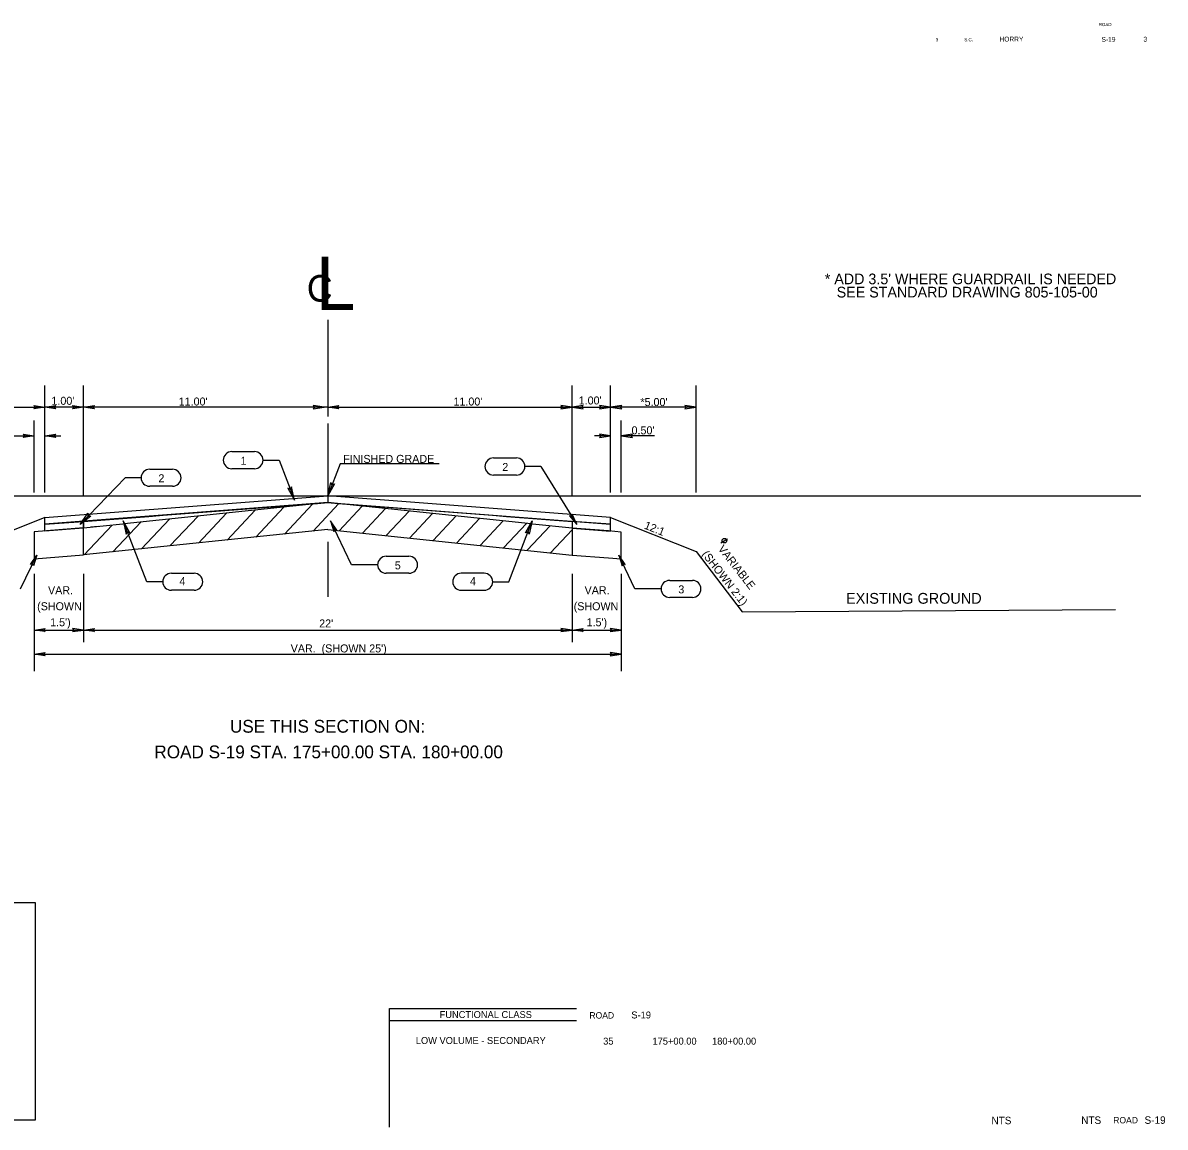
# Model space of a CAD drawing. Extents: x -8855 to -7217, y 44218 to 45252.
# Drawn here: x -8287 to -7217, y 44218 to 45252 of the extents above; entities that cross this region are included whole.
import ezdxf

# ---------------------------------------------------------------- set-up
doc = ezdxf.new("R2010")
doc.units = 0
for name, color, linetype in [('Default', 7, 'Continuous'), ('RD_EX_Misc', 7, 'Continuous'), ('RD_SHT_Bndy', 7, 'Continuous'), ('RD_SHT_TX', 7, 'Continuous'), ('RD_Sketch5', 7, 'Continuous'), ('RD_TX_TypSect', 7, 'Continuous'), ('RD_XS_Greenside', 7, 'Continuous')]:
    doc.layers.add(name, color=color, linetype=linetype)

msp = doc.modelspace()

# ---------------------------------------------------------------- linework, layer by layer
at = {"layer": 'Default'}
for p, q in [((-8825.7, 44809.3), (-8001.4, 44809.3)), ((-8001.4, 44809.3), (-7239.8, 44809.3)), ((-7626.9, 44768.9), (-7633.1, 44765.2)), ((-7613.3, 44700.8), (-7263.6, 44702.9))]:
    msp.add_line(p, q, dxfattribs=at)
for points in [[(-8266.4, 44892.5), (-8276.8, 44891), (-8275.2, 44892.5), (-8276.8, 44894)], [(-8266.4, 44892.5), (-8256, 44894), (-8257.6, 44892.5), (-8256, 44891)], [(-8230.3, 44892.5), (-8240.6, 44891), (-8239, 44892.5), (-8240.6, 44894)], [(-8230.3, 44892.5), (-8219.9, 44894), (-8221.5, 44892.5), (-8219.9, 44891)], [(-8004.6, 44892.5), (-8015, 44894), (-8013.4, 44892.5), (-8015, 44891)], [(-8001.4, 44892.5), (-7991, 44894), (-7992.6, 44892.5), (-7991, 44891)], [(-7772.5, 44892.5), (-7782.9, 44894), (-7781.3, 44892.5), (-7782.9, 44891)], [(-7772.5, 44892.5), (-7762.2, 44891), (-7763.8, 44892.5), (-7762.2, 44894)], [(-7736.4, 44892.5), (-7746.8, 44894), (-7745.2, 44892.5), (-7746.8, 44891)], [(-7736.4, 44892.5), (-7726, 44891), (-7727.6, 44892.5), (-7726, 44894)], [(-7656.4, 44892.5), (-7666.8, 44894), (-7665.2, 44892.5), (-7666.8, 44891)], [(-8276.4, 44865.6), (-8286.8, 44864.1), (-8285.2, 44865.6), (-8286.8, 44867.1)], [(-8266.4, 44865.6), (-8256, 44867.1), (-8257.6, 44865.6), (-8256, 44864.1)], [(-7736.4, 44865.6), (-7746.8, 44867.1), (-7745.2, 44865.6), (-7746.8, 44864.1)], [(-7726.4, 44865.6), (-7716, 44864.1), (-7717.6, 44865.6), (-7716, 44867.1)], [(-8230.3, 44785.4), (-8230.3, 44779.2), (-8266.4, 44776.3), (-8266.4, 44782.7)], [(-7998.8, 44786), (-7995.7, 44775.9), (-7995, 44778), (-7993, 44777.2)], [(-7772.5, 44785.5), (-7772.5, 44779.2), (-7736.4, 44776.3), (-7736.4, 44782.7)], [(-8274, 44753.9), (-8277.1, 44743.9), (-8277.8, 44746), (-8279.9, 44745.2)], [(-7728.8, 44753.9), (-7725.7, 44743.9), (-7725, 44746), (-7722.9, 44745.2)], [(-8276.4, 44683.7), (-8266, 44685.2), (-8267.6, 44683.7), (-8266, 44682.2)], [(-8230.3, 44683.7), (-8240.6, 44685.2), (-8239, 44683.7), (-8240.6, 44682.2)], [(-8230.3, 44683.7), (-8219.9, 44685.2), (-8221.5, 44683.7), (-8219.9, 44682.2)], [(-7772.5, 44683.7), (-7782.9, 44685.2), (-7781.3, 44683.7), (-7782.9, 44682.2)], [(-7772.5, 44683.7), (-7762.2, 44685.2), (-7763.8, 44683.7), (-7762.2, 44682.2)], [(-7726.4, 44683.7), (-7736.8, 44685.2), (-7735.2, 44683.7), (-7736.8, 44682.2)], [(-8276.4, 44661), (-8266, 44662.5), (-8267.6, 44661), (-8266, 44659.5)], [(-7726.4, 44661), (-7736.8, 44662.5), (-7735.2, 44661), (-7736.8, 44659.5)]]:
    msp.add_lwpolyline(points, close=True, dxfattribs=at)
msp.add_circle((-7629.8, 44767.4), 2.17, dxfattribs=at)
at = {"layer": 'RD_EX_Misc'}
for p, q in [((-8001.4, 44974.2), (-8001.4, 44883.7)), ((-8266.4, 44812.4), (-8266.4, 44912.7)), ((-8230.3, 44809.3), (-8230.3, 44912.7)), ((-7772.5, 44809.3), (-7772.5, 44912.7)), ((-7736.4, 44812.4), (-7736.4, 44912.7)), ((-7736.4, 44812.4), (-7736.4, 44912.7)), ((-7656.4, 44812.4), (-7656.4, 44912.6)), ((-8346.4, 44892.5), (-8266.4, 44892.5)), ((-8230.3, 44892.5), (-8266.4, 44892.5)), ((-8001.4, 44892.5), (-8230.3, 44892.5)), ((-8001.4, 44892.5), (-7772.5, 44892.5)), ((-7772.5, 44892.5), (-7736.4, 44892.5)), ((-7656.4, 44892.5), (-7736.4, 44892.5)), ((-8276.4, 44812.4), (-8276.4, 44880.1)), ((-8001.4, 44877), (-8001.4, 44809.3)), ((-7726.4, 44812.4), (-7726.4, 44880.1)), ((-8307.4, 44865.6), (-8276.4, 44865.6)), ((-8266.4, 44865.6), (-8251.4, 44865.6)), ((-7736.4, 44865.6), (-7751.4, 44865.6)), ((-7695.4, 44865.6), (-7726.4, 44865.6)), ((-8091.3, 44850.8), (-8070, 44850.8)), ((-7846.1, 44844.9), (-7824.7, 44844.9)), ((-8168.2, 44834.3), (-8146.8, 44834.3)), ((-8070, 44834.8), (-8091.3, 44834.8)), ((-8062, 44842.8), (-8047, 44842.8)), ((-7801.7, 44836.9), (-7816.7, 44836.9)), ((-7801.7, 44836.9), (-7768.1, 44782.6)), ((-8191.2, 44826.3), (-8233.4, 44782.6)), ((-8176.2, 44826.3), (-8191.2, 44826.3)), ((-7824.7, 44828.9), (-7846.1, 44828.9)), ((-8146.8, 44818.3), (-8168.2, 44818.3)), ((-8266.4, 44789), (-8001.4, 44809.3)), ((-8001.4, 44803), (-8266.4, 44782.7)), ((-8001.4, 44803), (-8192, 44783.2)), ((-8015.2, 44776.4), (-7991.2, 44802)), ((-8015.2, 44776.4), (-7991.2, 44802)), ((-7736.4, 44789), (-8001.4, 44809.3)), ((-8001.4, 44809.3), (-8001.4, 44803)), ((-8001.4, 44809.3), (-8001.4, 44803)), ((-7810.7, 44783.2), (-8001.4, 44803)), ((-8001.4, 44803), (-7736.4, 44782.7)), ((-8122.4, 44765.2), (-8096.1, 44793.1)), ((-8095.6, 44768), (-8069.3, 44795.9)), ((-8068.8, 44770.8), (-8042.6, 44798.7)), ((-8042, 44773.6), (-8015.8, 44801.5)), ((-7990.8, 44776.7), (-7969.2, 44799.7)), ((-7990.8, 44776.7), (-7969.2, 44799.7)), ((-7968.7, 44774.4), (-7947.2, 44797.4)), ((-7968.7, 44774.4), (-7947.2, 44797.4)), ((-7946.7, 44772.1), (-7925.2, 44795.1)), ((-7946.7, 44772.1), (-7925.2, 44795.1)), ((-7924.7, 44769.8), (-7903.2, 44792.8)), ((-7924.7, 44769.8), (-7903.2, 44792.8)), ((-8266.4, 44782.7), (-8266.4, 44789)), ((-8230.3, 44785.4), (-8168.9, 44790.1)), ((-8230.3, 44779.2), (-8230.3, 44785.4)), ((-8193.3, 44783), (-8230.3, 44779.2)), ((-8229.5, 44754), (-8203.3, 44782)), ((-8216.3, 44780.6), (-8223.2, 44779.9)), ((-8202.7, 44756.8), (-8176.5, 44784.8)), ((-8202.7, 44756.8), (-8176.5, 44784.8)), ((-8170.9, 44728.9), (-8193, 44785.9)), ((-8176, 44759.6), (-8149.7, 44787.6)), ((-8149.2, 44762.4), (-8122.9, 44790.4)), ((-7979.2, 44744.8), (-7998.8, 44786)), ((-7902.7, 44767.5), (-7881.1, 44790.5)), ((-7902.7, 44767.5), (-7881.1, 44790.5)), ((-7880.7, 44765.2), (-7859.1, 44788.2)), ((-7880.7, 44765.2), (-7859.1, 44788.2)), ((-7880.7, 44765.2), (-7859.1, 44788.2)), ((-7858.7, 44762.9), (-7837.1, 44785.9)), ((-7858.7, 44762.9), (-7837.1, 44785.9)), ((-7858.7, 44762.9), (-7837.1, 44785.9)), ((-7836.7, 44760.7), (-7815.1, 44783.6)), ((-7836.7, 44760.7), (-7815.1, 44783.6)), ((-7833.9, 44790.1), (-7772.5, 44785.5)), ((-7831.9, 44728.9), (-7809.8, 44785.9)), ((-7814.7, 44758.4), (-7793.1, 44781.3)), ((-7814.7, 44758.4), (-7793.1, 44781.3)), ((-7772.5, 44779.2), (-7809.5, 44783)), ((-7772.5, 44785.5), (-7772.5, 44779.2)), ((-7736.4, 44782.7), (-7736.4, 44789)), ((-8276.4, 44775.6), (-8276.4, 44750.3)), ((-8230.3, 44754), (-8230.3, 44779.4)), ((-8230.3, 44779.4), (-8230.3, 44779.4)), ((-8230.3, 44754), (-8230.3, 44779.4)), ((-8001.4, 44777.8), (-8230.3, 44754)), ((-8001.4, 44777.8), (-7772.5, 44753.9)), ((-7792.7, 44756.1), (-7772.5, 44777.5)), ((-7772.5, 44779.2), (-7772.5, 44753.9)), ((-7772.5, 44779.2), (-7772.5, 44753.9)), ((-7726.4, 44750.3), (-7726.4, 44775.5)), ((-8001.4, 44766.2), (-8001.4, 44714.8)), ((-8289.1, 44722.2), (-8274, 44753.9)), ((-7946.7, 44752.8), (-7925.3, 44752.8)), ((-7713.7, 44722.2), (-7728.8, 44753.9)), ((-7954.7, 44744.8), (-7979.2, 44744.8)), ((-8276.4, 44736.3), (-8276.4, 44645.2)), ((-8230.3, 44736.3), (-8230.3, 44672.4)), ((-8155.9, 44728.9), (-8170.9, 44728.9)), ((-8147.9, 44736.9), (-8126.5, 44736.9)), ((-7925.3, 44736.8), (-7946.7, 44736.8)), ((-7854.9, 44736.9), (-7876.3, 44736.9)), ((-7846.9, 44728.9), (-7831.9, 44728.9)), ((-7772.5, 44736.3), (-7772.5, 44672.4)), ((-7726.4, 44736.3), (-7726.4, 44645.2)), ((-7681.1, 44730.2), (-7659.8, 44730.2)), ((-8126.5, 44720.9), (-8147.9, 44720.9)), ((-7876.3, 44720.9), (-7854.9, 44720.9)), ((-7689.1, 44722.2), (-7713.7, 44722.2)), ((-7659.8, 44714.2), (-7681.1, 44714.2))]:
    msp.add_line(p, q, dxfattribs=at)
for points in [[(-8047, 44842.8), (-8032.4, 44805.3)], [(-7989.7, 44839.4), (-8001.4, 44809.3)], [(-7896.9, 44839.4), (-7989.7, 44839.4)], [(-8168.9, 44790.1), (-8155.6, 44791.2), (-8011.1, 44802.3), (-8001.4, 44803)], [(-8001.4, 44803), (-7991.7, 44802.3), (-7847.2, 44791.2), (-7833.9, 44790.1)], [(-8192, 44783.2), (-8193.3, 44783), (-8193.3, 44783)], [(-7809.5, 44783), (-7809.5, 44783), (-7810.7, 44783.2)], [(-8230.3, 44779.4), (-8264.7, 44776.5), (-8276.4, 44775.6)], [(-7726.4, 44775.5), (-7738.3, 44776.5), (-7772.5, 44779.2)], [(-8276.4, 44750.3), (-8264.7, 44751.2), (-8230.3, 44754)], [(-7772.5, 44753.9), (-7738.3, 44751.2), (-7726.4, 44750.3)], [(-8276.4, 44683.7), (-8230.3, 44683.7)], [(-8230.3, 44683.7), (-7772.5, 44683.7)], [(-7772.5, 44683.7), (-7726.4, 44683.7)], [(-8276.4, 44661), (-7726.4, 44661)]]:
    msp.add_lwpolyline(points, dxfattribs=at)
for points in [[(-7768.1, 44782.6), (-7772.3, 44792.2), (-7772.7, 44790), (-7774.8, 44790.6)], [(-8855, 44428.4), (-8275.6, 44428.4), (-8275.6, 44224.4), (-8855, 44224.4)]]:
    msp.add_lwpolyline(points, close=True, dxfattribs=at)
for centre, start, end in [((-8091.3, 44842.8), 90, 270), ((-8070, 44842.8), 270, 90), ((-7846.1, 44836.9), 90, 270), ((-7824.7, 44836.9), 270, 90), ((-8168.2, 44826.3), 90, 270), ((-8146.8, 44826.3), 270, 90), ((-7946.7, 44744.8), 90, 270), ((-7925.3, 44744.8), 270, 90), ((-8147.9, 44728.9), 90, 270), ((-8126.5, 44728.9), 270, 90), ((-7876.3, 44728.9), 90, 270), ((-7854.9, 44728.9), 270, 90), ((-7681.1, 44722.2), 90, 270), ((-7659.8, 44722.2), 270, 90)]:
    msp.add_arc(centre, 8, start, end, dxfattribs=at)
at = {"layer": 'RD_SHT_Bndy'}
for p, q in [((-7943.5, 44218), (-7943.5, 44329.1)), ((-7943.5, 44329.1), (-7768.5, 44329.1)), ((-7943.5, 44317.8), (-7768.5, 44317.8))]:
    msp.add_line(p, q, dxfattribs=at)
at = {"layer": 'RD_Sketch5'}
for points in [[(-8032.4, 44805.3), (-8035.3, 44817.8), (-8036.3, 44815.3), (-8038.7, 44816.5)], [(-8001.4, 44809.3), (-7998.5, 44821.8), (-7997.5, 44819.3), (-7995.1, 44820.5)], [(-8233.4, 44782.6), (-8226, 44793), (-8226, 44790.3), (-8223.4, 44790.4)], [(-8193, 44785.9), (-8190.2, 44773.4), (-8189.2, 44775.9), (-8186.8, 44774.7)], [(-7809.8, 44785.9), (-7812.6, 44773.4), (-7813.6, 44775.9), (-7816, 44774.7)]]:
    msp.add_lwpolyline(points, close=True, dxfattribs=at)
at = {"layer": 'RD_XS_Greenside'}
for p, q in [((-8266.4, 44789), (-8346.4, 44757.3)), ((-7736.4, 44789), (-7656.4, 44757.3)), ((-7656.4, 44757.3), (-7613.3, 44700.8))]:
    msp.add_line(p, q, dxfattribs=at)

# ---------------------------------------------------------------- texts
at = {"layer": 'Default'}
for s, p in [('S-19', (-7717, 44319.8)), ('35', (-7743.4, 44295.3)), ('175+00.00', (-7697.2, 44295.3)), ('180+00.00', (-7641.4, 44295.3))]:
    msp.add_text(s, height=6.5, dxfattribs=at).set_placement(p)
at = {"layer": 'RD_EX_Misc'}
for s, height, p in [('L', 50, (-8012.7, 44983.5)), ('C', 25, (-8021, 44991.3)), ("1.00'", 7.5, (-8260.2, 44894.7)), ("1.00'", 7.5, (-7766.3, 44895)), ("*5.00'", 7.5, (-7708.5, 44893.5)), ("0.50'", 7.5, (-7716.8, 44867)), ('1', 7.5, (-8083.1, 44838.5)), ('2', 7.5, (-7837.9, 44832.7)), ('2', 7.5, (-8160, 44822.1)), ('5', 7.5, (-7938.6, 44740.5)), ('4', 7.5, (-8140.3, 44725.7)), ('4', 7.5, (-7868.2, 44725.7)), ('VAR.', 7.5, (-8263.4, 44717.2)), ('VAR.', 7.5, (-7760.8, 44717.2)), ('3', 7.5, (-7673, 44718)), ('EXISTING GROUND ', 10.119, (-7515.9, 44708.3)), ('(SHOWN', 7.5, (-8273.6, 44702.2)), ('(SHOWN', 7.5, (-7771, 44702.2)), ("1.5')", 7.5, (-8261.4, 44687.2)), ("1.5')", 7.5, (-7758.9, 44687.2)), ("22'", 7.5, (-8009.4, 44686.1)), ("VAR.  (SHOWN 25') ", 7.5, (-8036.1, 44662.7)), ('USE THIS SECTION ON:', 12, (-8093, 44587.5)), ('ROAD S-19 STA. 175+00.00 STA. 180+00.00', 12, (-8163.8, 44563.5)), ('NTS', 7, (-7379.7, 44220.7)), ('NTS', 7, (-7295.6, 44221)), ('S-19', 7, (-7236.3, 44221.1))]:
    msp.add_text(s, height=height, dxfattribs=at).set_placement(p)
for s, rotation, p in [("11.00'", 360, (-8141, 44894)), ("11.00'", 360, (-7883.6, 44894)), ('FINISHED GRADE', 0.0434, (-7986.9, 44840.2)), ('12:1', 338.3553, (-7705.6, 44778.9)), ('VARIABLE', 307.9739, (-7636.3, 44759.6)), ('(SHOWN 2:1)', 307.9739, (-7651.4, 44754.5))]:
    msp.add_text(s, height=7.5, rotation=rotation, dxfattribs=at).set_placement(p)
at = {"layer": 'RD_SHT_TX'}
for s, height, p in [('ROAD', 3, (-7279.2, 45249.4)), ('3', 3, (-7431.9, 45235.2)), ('S.C.', 3, (-7405.1, 45235.2)), ('FUNCTIONAL CLASS', 6.5, (-7896.6, 44320.2)), ('ROAD', 6, (-7756.3, 44319.7)), ('LOW VOLUME - SECONDARY', 6.5, (-7918.9, 44295.9)), ('ROAD', 6, (-7265.6, 44221.5))]:
    msp.add_text(s, height=height, dxfattribs=at).set_placement(p)
for s, p in [('HORRY', (-7372.2, 45235)), ('S-19', (-7276.6, 45234.7)), ('3', (-7237.3, 45234.9))]:
    msp.add_text(s, height=4.5, rotation=0.0746, dxfattribs=at).set_placement(p)
at = {"layer": 'RD_TX_TypSect'}
for s, p in [("* ADD 3.5' WHERE GUARDRAIL IS NEEDED", (-7535.8, 45007.6)), ('   SEE STANDARD DRAWING 805-105-00', (-7535.8, 44995.2))]:
    msp.add_text(s, height=10, dxfattribs=at).set_placement(p)

doc.saveas('drawing.dxf')
